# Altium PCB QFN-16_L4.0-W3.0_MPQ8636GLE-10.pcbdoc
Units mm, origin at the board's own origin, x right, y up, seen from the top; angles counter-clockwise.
Board outline 16.04 x 17.3 mm, 2 copper layers (Top Layer, Bottom Layer), stack 0 mm thick; 1 components, 0 nets, 16 pads, 0 vias.
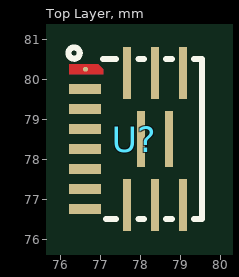
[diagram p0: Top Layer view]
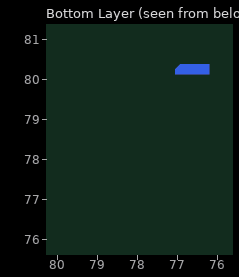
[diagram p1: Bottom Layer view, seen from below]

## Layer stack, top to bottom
Top Layer: signal copper (thickness not stored)
Bottom Layer: signal copper (thickness not stored)

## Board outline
85.891,69.85 69.85,69.85 69.85,87.15 85.891,87.15

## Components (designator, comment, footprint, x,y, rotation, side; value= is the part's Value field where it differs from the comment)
U? "" QFN-16_L4.0-W3.0_MPQ8636GLE-10 77.841,78.5 r0 top

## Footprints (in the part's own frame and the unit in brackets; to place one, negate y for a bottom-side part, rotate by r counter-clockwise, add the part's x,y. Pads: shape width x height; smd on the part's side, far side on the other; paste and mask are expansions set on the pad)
QFN-16_L4.0-W3.0_MPQ8636GLE-10 [mm]
  round 0.122 smd: 1(-1.214,1.747)
  rect 0.8x0.25 smd paste+0 mask+0.05: 2(-1.225,1.25) 3(-1.225,0.75) 4(-1.225,0.25) 5(-1.225,-0.25) 6(-1.225,-0.75) 7(-1.225,-1.25) 8(-1.225,-1.75)
  rect 0.2x1.3 smd paste+0 mask+0.05: 9(-0.175,-1.65) 10(0.525,-1.65) 11(1.225,-1.65) 12(1.225,1.65) 13(0.525,1.65) 14(-0.175,1.65)
  rect 0.2x1.4 smd paste+0 mask+0.05: 15(0.175,0) 16(0.875,0)
  Top Layer region: -1.625,1.875 -0.899,1.875 -0.775,1.751 -0.775,1.625 -1.625,1.625
  Bottom Layer region: -1.625,1.875 -0.899,1.875 -0.775,1.751 -0.775,1.625 -1.625,1.625
  Multi-Layer region: -1.625,1.875 -0.899,1.875 -0.775,1.751 -0.775,1.625 -1.625,1.625
  silkscreen extent -1.64,-2 1.7,2.29

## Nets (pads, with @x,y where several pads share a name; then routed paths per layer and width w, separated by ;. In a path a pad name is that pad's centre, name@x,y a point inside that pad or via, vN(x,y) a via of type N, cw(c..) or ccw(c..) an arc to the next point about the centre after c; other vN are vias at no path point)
pads on no net: U?.1 U?.2 U?.3 U?.4 U?.5 U?.6 U?.7 U?.8 U?.9 U?.10 U?.11 U?.12 U?.13 U?.14 U?.15 U?.16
